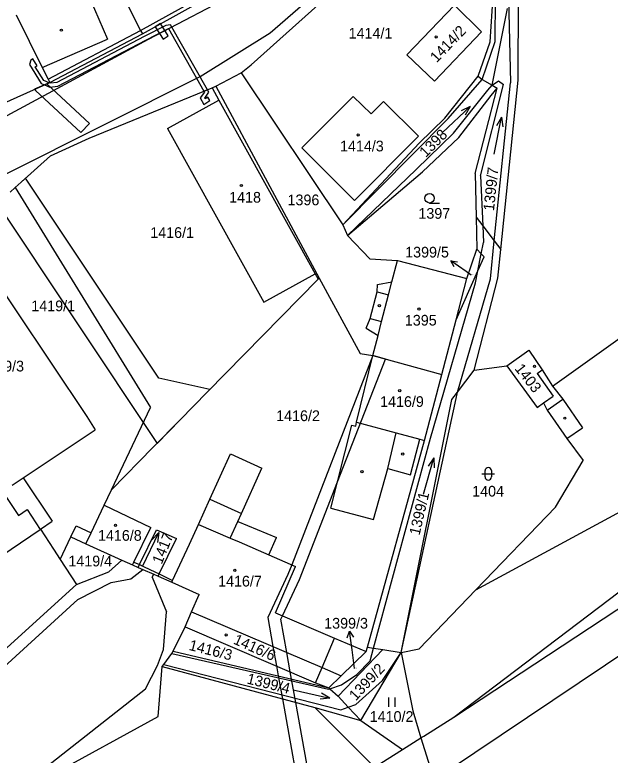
# Model space of a CAD drawing. Extents: x -785744 to -782822, y -1067550 to -1063910.
# Drawn here: x -784334.2 to -784239.5, y -1065522 to -1065404.3 of the extents above; entities that cross this region are included whole.
import ezdxf

# ---------------------------------------------------------------- set-up
doc = ezdxf.new("R2010")
doc.units = 0
for name, color, linetype in [('Hranice parcel', 7, 'Continuous'), ('Parcelní čísla', 7, 'Continuous'), ('Pop_ČP_popisy', 7, 'Continuous'), ('Vnitřní kresba', 7, 'Continuous'), ('Věcná břemena k části', 7, 'Continuous'), ('Značky budov', 7, 'Continuous'), ('Značky kultur', 7, 'Continuous')]:
    doc.layers.add(name, color=color, linetype=linetype)

msp = doc.modelspace()

# ---------------------------------------------------------------- linework, layer by layer
at = {"layer": 'Hranice parcel'}
for p, q in [((-784325.23, -1065487.26), (-784324.42, -1065485.54)), ((-784324.42, -1065485.54), (-784322.05, -1065486.66)), ((-784326.93, -1065490.87), (-784325.23, -1065487.26)), ((-784328.01, -1065489.21), (-784326.93, -1065490.87)), ((-784326.93, -1065490.87), (-784324.37, -1065494.83))]:
    msp.add_line(p, q, dxfattribs=at)
for points in [[(-784254.13, -1065414.69), (-784254.05, -1065388.02)], [(-784296.61, -1065412.23), (-784275.88, -1065393.63)], [(-784318.51, -1065398.12), (-784314.18, -1065406.77)], [(-784313.89, -1065407.3), (-784297.91, -1065398.39)], [(-784258.62, -1065408.55), (-784258.1, -1065401.22)], [(-784271.83, -1065410.63), (-784264.26, -1065402.73)], [(-784264.26, -1065402.73), (-784259.96, -1065406.99)], [(-784258.3, -1065415.48), (-784255.87, -1065403.26)], [(-784333.94, -1065404.27), (-784329.79, -1065412.66)], [(-784328.61, -1065415.04), (-784313.89, -1065407.3)], [(-784314.18, -1065406.77), (-784313.89, -1065407.3)], [(-784267.46, -1065414.82), (-784259.96, -1065406.99)], [(-784260.53, -1065414.01), (-784258.62, -1065408.55)], [(-784271.83, -1065410.63), (-784267.46, -1065414.82)], [(-784298.16, -1065413.48), (-784296.61, -1065412.23)], [(-784329.79, -1065412.66), (-784328.87, -1065414.51)], [(-784302.19, -1065415.64), (-784298.16, -1065413.48)], [(-784298.16, -1065413.48), (-784282.01, -1065437.69)], [(-784328.87, -1065414.51), (-784328.61, -1065415.04)], [(-784265.83, -1065420.7), (-784260.53, -1065414.01)], [(-784260.53, -1065414.01), (-784259.86, -1065414.56)], [(-784259.86, -1065414.56), (-784258.3, -1065415.48)], [(-784256.89, -1065441.59), (-784254.13, -1065414.69)], [(-784353.07, -1065426.03), (-784328.61, -1065415.04)], [(-784322.36, -1065423.91), (-784302.8, -1065415.89)], [(-784302.8, -1065415.89), (-784302.19, -1065415.64)], [(-784302.19, -1065415.64), (-784285.76, -1065446.13)], [(-784260.98, -1065429.49), (-784257.51, -1065415.94)], [(-784258.44, -1065417.09), (-784257.51, -1065415.94)], [(-784258.3, -1065415.48), (-784257.51, -1065415.94)], [(-784263.58, -1065423.8), (-784258.44, -1065417.09)], [(-784309.88, -1065422.37), (-784301.72, -1065417.85)], [(-784301.72, -1065417.85), (-784286.43, -1065445.44)], [(-784288.54, -1065425.41), (-784280.4, -1065417.25)], [(-784280.4, -1065417.25), (-784277.52, -1065420.02)], [(-784277.52, -1065420.02), (-784275.54, -1065418.04)], [(-784275.54, -1065418.04), (-784269.99, -1065423.58)], [(-784269.9, -1065424.7), (-784265.83, -1065420.7)], [(-784309.88, -1065422.37), (-784294.59, -1065449.96)], [(-784328.51, -1065426.7), (-784322.36, -1065423.91)], [(-784280.17, -1065433.79), (-784269.99, -1065423.58)], [(-784269.34, -1065429.22), (-784263.58, -1065423.8)], [(-784282.01, -1065437.69), (-784269.9, -1065424.7)], [(-784288.54, -1065425.41), (-784280.17, -1065433.79)], [(-784333.15, -1065430.88), (-784328.51, -1065426.7)], [(-784281.3, -1065439.38), (-784269.34, -1065429.22)], [(-784260.98, -1065429.49), (-784260.84, -1065436.43)], [(-784334.08, -1065431.72), (-784333.15, -1065430.88)], [(-784334.9, -1065432.46), (-784334.08, -1065431.72)], [(-784334.08, -1065431.72), (-784312.61, -1065466.7)], [(-784260.84, -1065436.43), (-784260.73, -1065441.54)], [(-784260.84, -1065436.43), (-784259.78, -1065437.82)], [(-784282.01, -1065437.69), (-784281.3, -1065439.38)], [(-784259.78, -1065437.82), (-784257.95, -1065440.21)], [(-784281.3, -1065439.38), (-784277.72, -1065443.08)], [(-784257.95, -1065440.21), (-784256.89, -1065441.59)], [(-784262.31, -1065446.22), (-784260.73, -1065441.54)], [(-784260.73, -1065441.54), (-784260.02, -1065442.28)], [(-784257.36, -1065446.16), (-784256.89, -1065441.59)], [(-784339.79, -1065442.71), (-784322.71, -1065468.16)], [(-784260.55, -1065445), (-784259.55, -1065442.76)], [(-784260.02, -1065442.28), (-784259.55, -1065442.76)], [(-784277.72, -1065443.08), (-784273.34, -1065443.33)], [(-784274.21, -1065446.71), (-784273.34, -1065443.33)], [(-784273.34, -1065443.33), (-784262.31, -1065446.22)], [(-784264.02, -1065452.76), (-784260.55, -1065445)], [(-784248.7, -1065463.3), (-784221.99, -1065444.26)], [(-784303.58, -1065464.28), (-784285.95, -1065446.31)], [(-784294.59, -1065449.96), (-784286.43, -1065445.44)], [(-784285.95, -1065446.31), (-784285.76, -1065446.13)], [(-784285.76, -1065446.13), (-784279.28, -1065458.15)], [(-784264.02, -1065452.76), (-784262.31, -1065446.22)], [(-784261.14, -1065460.78), (-784257.36, -1065446.16)], [(-784276.59, -1065448.34), (-784276.53, -1065447.13)], [(-784276.53, -1065447.13), (-784274.21, -1065446.71)], [(-784277.69, -1065452.58), (-784276.59, -1065448.34)], [(-784278.31, -1065454.07), (-784277.69, -1065452.58)], [(-784266.29, -1065461.45), (-784264.02, -1065452.76)], [(-784278.31, -1065454.07), (-784276.42, -1065455.25)], [(-784277.25, -1065458.45), (-784276.42, -1065455.25)], [(-784279.28, -1065458.15), (-784277.25, -1065458.45)], [(-784255.97, -1065460.11), (-784252.43, -1065457.59)], [(-784252.43, -1065457.59), (-784250.35, -1065460.73)], [(-784279.83, -1065469.05), (-784277.25, -1065458.45)], [(-784277.25, -1065458.45), (-784266.29, -1065461.45)], [(-784265.21, -1065524.39), (-784169.44, -1065460.07)], [(-784261.14, -1065460.78), (-784255.97, -1065460.11)], [(-784255.97, -1065460.11), (-784251.14, -1065466.73)], [(-784269.04, -1065471.94), (-784266.29, -1065461.45)], [(-784263.77, -1065464.25), (-784261.14, -1065460.78)], [(-784250.35, -1065460.73), (-784248.7, -1065463.3)], [(-784264.37, -1065515.96), (-784195.4, -1065463.66)], [(-784248.7, -1065463.3), (-784247.06, -1065465.4)], [(-784307.87, -1065468.67), (-784303.58, -1065464.28)], [(-784264.67, -1065465.45), (-784263.77, -1065464.25)], [(-784247.06, -1065465.4), (-784243.93, -1065469.93)], [(-784272.77, -1065505.68), (-784264.67, -1065465.45)], [(-784251.14, -1065466.73), (-784250.11, -1065465.98)], [(-784250.11, -1065465.98), (-784249.54, -1065467.11)], [(-784318.81, -1065479.81), (-784312.61, -1065466.7)], [(-784249.54, -1065467.11), (-784246.41, -1065471.64)], [(-784322.71, -1065468.16), (-784321.4, -1065470.26)], [(-784312.17, -1065473.04), (-784307.87, -1065468.67)], [(-784283.91, -1065482.7), (-784280.58, -1065469.52)], [(-784280.58, -1065469.52), (-784279.98, -1065469.66)], [(-784279.98, -1065469.66), (-784279.83, -1065469.05)], [(-784246.41, -1065471.64), (-784243.93, -1065469.93)], [(-784332.82, -1065477.89), (-784321.4, -1065470.26)], [(-784278.12, -1065504.82), (-784269.04, -1065471.94)], [(-784271.28, -1065477.43), (-784269.76, -1065471.74)], [(-784269.76, -1065471.74), (-784269.04, -1065471.94)], [(-784246.41, -1065471.64), (-784243.8, -1065475.13)], [(-784318.81, -1065479.81), (-784312.17, -1065473.04)], [(-784303.16, -1065481.3), (-784299.9, -1065474.1)], [(-784299.9, -1065474.1), (-784294.89, -1065476.37)], [(-784248.23, -1065482.58), (-784243.8, -1065475.13)], [(-784298.15, -1065483.57), (-784294.89, -1065476.37)], [(-784277.13, -1065484.5), (-784274.89, -1065476.42)], [(-784274.89, -1065476.42), (-784271.28, -1065477.43)], [(-784332.82, -1065477.89), (-784328.21, -1065484.8)], [(-784260.87, -1065495.71), (-784230.15, -1065479.08)], [(-784319.95, -1065482.23), (-784318.81, -1065479.81)], [(-784304.98, -1065485.31), (-784303.16, -1065481.3)], [(-784322.05, -1065486.66), (-784319.95, -1065482.23)], [(-784319.95, -1065482.23), (-784312.53, -1065485.78)], [(-784283.91, -1065482.7), (-784277.13, -1065484.5)], [(-784260.87, -1065495.71), (-784248.23, -1065482.58)], [(-784298.73, -1065484.84), (-784298.15, -1065483.57)], [(-784330.06, -1065486.04), (-784328.21, -1065484.8)], [(-784306.4, -1065488.45), (-784304.98, -1065485.31)], [(-784298.73, -1065484.84), (-784292.58, -1065487.39)], [(-784337.91, -1065491.33), (-784330.13, -1065486.09)], [(-784330.13, -1065486.09), (-784330.06, -1065486.04)], [(-784330.06, -1065486.04), (-784328.01, -1065489.21)], [(-784315.22, -1065491.28), (-784312.53, -1065485.78)], [(-784314.35, -1065491.69), (-784311.65, -1065486.16)], [(-784311.65, -1065486.16), (-784308.47, -1065487.55)], [(-784322.86, -1065488.38), (-784322.05, -1065486.66)], [(-784311.2, -1065493.18), (-784308.47, -1065487.55)], [(-784293.78, -1065490.14), (-784292.58, -1065487.39)], [(-784322.86, -1065488.38), (-784317.15, -1065490.98)], [(-784309.07, -1065494.2), (-784306.4, -1065488.45)], [(-784264.37, -1065515.96), (-784223.44, -1065488.95)], [(-784319.21, -1065492.84), (-784317.15, -1065490.98)], [(-784317.15, -1065490.98), (-784315.43, -1065491.75)], [(-784315.43, -1065491.75), (-784315.22, -1065491.28)], [(-784293.78, -1065490.14), (-784289.57, -1065491.99)], [(-784315.43, -1065491.75), (-784314.56, -1065492.13)], [(-784314.56, -1065492.13), (-784314.35, -1065491.69)], [(-784314.56, -1065492.13), (-784313.8, -1065492.46)], [(-784313.8, -1065492.46), (-784312.06, -1065493.22)], [(-784292.73, -1065499.34), (-784289.57, -1065491.99)], [(-784324.37, -1065494.83), (-784319.21, -1065492.84)], [(-784312.06, -1065493.22), (-784311.37, -1065493.53)], [(-784311.37, -1065493.53), (-784311.2, -1065493.18)], [(-784311.37, -1065493.53), (-784309.2, -1065494.48)], [(-784351.69, -1065519.66), (-784324.37, -1065494.83)], [(-784309.2, -1065494.48), (-784309.07, -1065494.2)], [(-784309.2, -1065494.48), (-784304.84, -1065496.42)], [(-784269.89, -1065505.08), (-784260.87, -1065495.71)], [(-784306.05, -1065499.18), (-784304.84, -1065496.42)], [(-784307.09, -1065501.56), (-784306.05, -1065499.18)], [(-784306.05, -1065499.18), (-784285.33, -1065508.05)], [(-784292.73, -1065499.34), (-784283.32, -1065503.38)], [(-784308.97, -1065505.47), (-784307.09, -1065501.56)], [(-784307.09, -1065501.56), (-784286.36, -1065510.46)], [(-784285.33, -1065508.05), (-784283.32, -1065503.38)], [(-784282.78, -1065512.6), (-784275.65, -1065505.21)], [(-784278.31, -1065505.52), (-784278.12, -1065504.82)], [(-784278.12, -1065504.82), (-784277.13, -1065504.98)], [(-784277.13, -1065504.98), (-784275.65, -1065505.21)], [(-784275.65, -1065505.21), (-784272.77, -1065505.68)], [(-784272.77, -1065505.68), (-784269.89, -1065505.08)], [(-784310.49, -1065507.55), (-784309.22, -1065505.81)], [(-784309.22, -1065505.81), (-784308.97, -1065505.47)], [(-784308.97, -1065505.47), (-784284.27, -1065511.27)], [(-784282.28, -1065509.35), (-784278.31, -1065505.52)], [(-784279.17, -1065516.47), (-784272.77, -1065505.68)], [(-784272.77, -1065505.68), (-784270.92, -1065514.95)], [(-784310.75, -1065507.9), (-784310.49, -1065507.55)], [(-784311.36, -1065515.82), (-784310.75, -1065507.9)], [(-784310.75, -1065507.9), (-784286.46, -1065514.42)], [(-784286.36, -1065510.46), (-784285.33, -1065508.05)], [(-784285.33, -1065508.05), (-784282.28, -1065509.35)], [(-784284.27, -1065511.27), (-784282.28, -1065509.35)], [(-784284.27, -1065511.27), (-784284.1, -1065511.42)], [(-784284.1, -1065511.42), (-784282.78, -1065512.6)], [(-784282.78, -1065512.6), (-784281.15, -1065514.35)], [(-784286.46, -1065514.42), (-784279.17, -1065516.47)], [(-784281.15, -1065514.35), (-784279.17, -1065516.47)], [(-784328.38, -1065525.17), (-784311.36, -1065515.82)], [(-784270.92, -1065514.95), (-784269.6, -1065519.25)], [(-784269.16, -1065518.98), (-784264.37, -1065515.96)], [(-784279.17, -1065516.47), (-784272.55, -1065521.1)], [(-784272.55, -1065521.1), (-784269.6, -1065519.25)], [(-784269.6, -1065519.25), (-784269.16, -1065518.98)], [(-784269.6, -1065519.25), (-784267.63, -1065525.66)], [(-784276.98, -1065523.88), (-784272.55, -1065521.1)]]:
    msp.add_lwpolyline(points, dxfattribs=at)
at = {"layer": 'Pop_ČP_popisy'}
for p, q in [((-784262.42, -1065445.1), (-784264.87, -1065443.37)), ((-784280.56, -1065505.25), (-784280.95, -1065502.28))]:
    msp.add_line(p, q, dxfattribs=at)
for points in [[(-784264.34, -1065444.36), (-784264.87, -1065443.37), (-784263.77, -1065443.54)], [(-784261.62, -1065445.66), (-784262.42, -1065445.1)], [(-784281.32, -1065503.33), (-784280.95, -1065502.28), (-784280.33, -1065503.2)], [(-784280.17, -1065508.19), (-784280.56, -1065505.25)]]:
    msp.add_lwpolyline(points, dxfattribs=at)
at = {"layer": 'Vnitřní kresba'}
for points in [[(-784314.18, -1065406.77), (-784298.2, -1065397.86)], [(-784293.59, -1065407.12), (-784283.18, -1065398.1)], [(-784312.91, -1065408.16), (-784297.89, -1065400.23)], [(-784322.2, -1065401.72), (-784319.44, -1065408.15)], [(-784257.82, -1065408.51), (-784257.74, -1065401.55)], [(-784255.68, -1065401.64), (-784255.35, -1065415.08)], [(-784328.87, -1065414.51), (-784314.18, -1065406.77)], [(-784304.68, -1065414.1), (-784293.59, -1065407.12)], [(-784336.08, -1065420.66), (-784312.91, -1065408.16)], [(-784329.79, -1065412.66), (-784319.44, -1065408.15)], [(-784259.86, -1065414.56), (-784257.82, -1065408.51)], [(-784335.41, -1065429.53), (-784304.68, -1065414.1)], [(-784265.26, -1065420.75), (-784259.86, -1065414.56)], [(-784258.3, -1065415.48), (-784257.27, -1065414.76)], [(-784257.27, -1065414.76), (-784256.49, -1065415.35)], [(-784302.8, -1065415.89), (-784301.72, -1065417.85)], [(-784260.14, -1065429.88), (-784256.49, -1065415.35)], [(-784258.96, -1065416.26), (-784258.3, -1065415.48)], [(-784257.95, -1065440.21), (-784255.35, -1065415.08)], [(-784264.41, -1065423.08), (-784258.96, -1065416.26)], [(-784282.01, -1065437.69), (-784265.26, -1065420.75)], [(-784270.38, -1065428.87), (-784264.41, -1065423.08)], [(-784281.3, -1065439.38), (-784270.38, -1065428.87)], [(-784260.14, -1065429.88), (-784259.78, -1065437.82)], [(-784259.78, -1065437.82), (-784259.66, -1065440.47)], [(-784260.02, -1065442.28), (-784259.66, -1065440.47)], [(-784258.57, -1065446.23), (-784257.95, -1065440.21)], [(-784260.55, -1065445), (-784260.02, -1065442.28)], [(-784260.92, -1065446.87), (-784260.55, -1065445)], [(-784286.43, -1065445.44), (-784285.95, -1065446.31)], [(-784263.77, -1065464.25), (-784258.57, -1065446.23)], [(-784274.75, -1065448.81), (-784274.21, -1065446.71)], [(-784268.08, -1065471.6), (-784260.92, -1065446.87)], [(-784276.59, -1065448.34), (-784274.75, -1065448.81)], [(-784275.85, -1065453.05), (-784274.75, -1065448.81)], [(-784277.69, -1065452.58), (-784275.85, -1065453.05)], [(-784276.42, -1065455.25), (-784275.85, -1065453.05)], [(-784251.14, -1065461.29), (-784250.35, -1065460.73)], [(-784251.14, -1065461.29), (-784248.61, -1065464.89)], [(-784272.77, -1065505.68), (-784264.03, -1065465.3)], [(-784264.03, -1065465.3), (-784263.77, -1065464.25)], [(-784250.11, -1065465.98), (-784248.61, -1065464.89)], [(-784249.54, -1065467.11), (-784247.06, -1065465.4)], [(-784279.83, -1065469.05), (-784273.57, -1065470.72)], [(-784274.89, -1065476.42), (-784273.57, -1065470.72)], [(-784273.57, -1065470.72), (-784269.76, -1065471.74)], [(-784277.13, -1065504.98), (-784268.08, -1065471.6)], [(-784334.58, -1065479.06), (-784332.82, -1065477.89)], [(-784336.12, -1065480.09), (-784333.6, -1065483.86)], [(-784303.16, -1065481.3), (-784298.15, -1065483.57)], [(-784333.6, -1065483.86), (-784332.21, -1065482.94)], [(-784332.21, -1065482.94), (-784330.13, -1065486.09)], [(-784304.98, -1065485.31), (-784299.92, -1065487.47)], [(-784299.92, -1065487.47), (-784298.73, -1065484.84)], [(-784325.23, -1065487.26), (-784322.86, -1065488.38)], [(-784299.92, -1065487.47), (-784298.5, -1065488.07)], [(-784298.5, -1065488.07), (-784293.78, -1065490.14)], [(-784315.22, -1065491.28), (-784314.35, -1065491.69)], [(-784315.73, -1065493.94), (-784313.8, -1065492.46)], [(-784314.35, -1065491.69), (-784313.6, -1065492.04)], [(-784313.6, -1065492.04), (-784311.89, -1065492.85)], [(-784312.32, -1065493.7), (-784312.06, -1065493.22)], [(-784311.89, -1065492.85), (-784311.2, -1065493.18)], [(-784311.2, -1065493.18), (-784309.07, -1065494.2)], [(-784324.13, -1065497.26), (-784318.87, -1065494.54)], [(-784318.87, -1065494.54), (-784315.73, -1065493.94)], [(-784312.32, -1065493.7), (-784310.06, -1065499.22)], [(-784354.42, -1065524.84), (-784324.13, -1065497.26)], [(-784310.53, -1065505.21), (-784310.06, -1065499.22)], [(-784283.32, -1065503.38), (-784278.31, -1065505.52)], [(-784311.46, -1065507.74), (-784310.53, -1065505.21)], [(-784277.68, -1065507), (-784277.13, -1065504.98)], [(-784309.22, -1065505.81), (-784284.3, -1065511.49)], [(-784275.72, -1065510.13), (-784272.77, -1065505.68)], [(-784313.37, -1065511.43), (-784311.46, -1065507.74)], [(-784310.49, -1065507.55), (-784282.33, -1065514.77)], [(-784279.81, -1065509.18), (-784277.68, -1065507)], [(-784282.23, -1065510.81), (-784279.81, -1065509.18)], [(-784279.94, -1065513.92), (-784275.72, -1065510.13)], [(-784286.36, -1065510.46), (-784284.27, -1065511.27)], [(-784284.1, -1065511.42), (-784282.23, -1065510.81)], [(-784329.77, -1065524.34), (-784313.37, -1065511.43)], [(-784284.3, -1065511.49), (-784284.1, -1065511.42)], [(-784286.46, -1065514.42), (-784276.98, -1065523.88)], [(-784282.33, -1065514.77), (-784281.15, -1065514.35)], [(-784281.15, -1065514.35), (-784279.94, -1065513.92)]]:
    msp.add_lwpolyline(points, dxfattribs=at)
at = {"layer": 'Věcná břemena k části'}
for points in [[(-784310.13, -1065405.97), (-784313.61, -1065407.75)], [(-784313.33, -1065408.29), (-784309.75, -1065406.45)], [(-784310.99, -1065405.68), (-784311.87, -1065406.17)], [(-784311.87, -1065406.17), (-784310.6, -1065408.17)], [(-784309.76, -1065407.63), (-784310.99, -1065405.68)], [(-784309.39, -1065405.86), (-784310.13, -1065405.97)], [(-784309.75, -1065406.45), (-784304.1, -1065416.42)], [(-784303.54, -1065416.19), (-784309.39, -1065405.86)], [(-784310.6, -1065408.17), (-784309.76, -1065407.63)], [(-784313.61, -1065407.75), (-784327.48, -1065415.06)], [(-784327.3, -1065415.64), (-784313.33, -1065408.29)], [(-784331.64, -1065411.46), (-784331.84, -1065412.2)], [(-784331.84, -1065412.2), (-784329.97, -1065415.18)], [(-784331.3, -1065411.26), (-784331.64, -1065411.46)], [(-784330.63, -1065412.41), (-784331.3, -1065411.26)], [(-784330.9, -1065412.57), (-784330.63, -1065412.41)], [(-784329.57, -1065414.7), (-784330.9, -1065412.57)], [(-784328.69, -1065415.08), (-784329.57, -1065414.7)], [(-784329.05, -1065415.24), (-784331.01, -1065416.12)], [(-784329.97, -1065415.18), (-784329.44, -1065415.41)], [(-784328.69, -1065415.08), (-784329.44, -1065415.41)], [(-784329.44, -1065415.41), (-784328.69, -1065415.08)], [(-784329.44, -1065415.41), (-784328.59, -1065415.78)], [(-784322.28, -1065421.53), (-784329.05, -1065415.24)], [(-784328.49, -1065415.16), (-784328.69, -1065415.08)], [(-784328.59, -1065415.78), (-784327.3, -1065415.64)], [(-784327.48, -1065415.06), (-784328.49, -1065415.16)], [(-784331.01, -1065416.12), (-784330.85, -1065416.29)], [(-784330.85, -1065416.29), (-784323.64, -1065422.99)], [(-784304.03, -1065416.55), (-784304.69, -1065417.47)], [(-784303.54, -1065416.19), (-784304.1, -1065416.42)], [(-784304.1, -1065416.42), (-784303.54, -1065416.19)], [(-784304.1, -1065416.42), (-784304.03, -1065416.55)], [(-784303.97, -1065417.51), (-784303.31, -1065416.59)], [(-784303.31, -1065416.59), (-784303.54, -1065416.19)], [(-784304.69, -1065417.47), (-784304.09, -1065418.51)], [(-784304.09, -1065418.51), (-784303.16, -1065417.88)], [(-784303.89, -1065417.65), (-784303.97, -1065417.51)], [(-784303.5, -1065417.38), (-784303.89, -1065417.65)], [(-784303.16, -1065417.88), (-784303.5, -1065417.38)], [(-784323.64, -1065422.99), (-784322.28, -1065421.53)], [(-784333.15, -1065430.88), (-784334.08, -1065431.72)], [(-784332.47, -1065430.27), (-784333.15, -1065430.88)], [(-784311.26, -1065462.04), (-784332.47, -1065430.27)], [(-784334.08, -1065431.72), (-784334.9, -1065432.46)], [(-784337.35, -1065433.77), (-784311.55, -1065472.41)], [(-784285.98, -1065533.43), (-784286.13, -1065532.33), (-784286.36, -1065531.04), (-784289.5, -1065513.6), (-784290.17, -1065509.89), (-784290.37, -1065508.74), (-784290.93, -1065505.65), (-784291.88, -1065500.36), (-784291.62, -1065499.81), (-784288.92, -1065494.07), (-784282.86, -1065478.53), (-784275.24, -1065459), (-784277.25, -1065458.45), (-784290.15, -1065491.73), (-784290.75, -1065493.28), (-784293.96, -1065500.08), (-784293.13, -1065504.71), (-784292.58, -1065507.79), (-784292.29, -1065509.39), (-784291.63, -1065513.03), (-784288.15, -1065532.41), (-784287.96, -1065533.75)], [(-784303.15, -1065463.85), (-784311.26, -1065462.04)], [(-784303.58, -1065464.28), (-784303.15, -1065463.85)], [(-784307.87, -1065468.67), (-784303.58, -1065464.28)], [(-784311.55, -1065472.41), (-784307.87, -1065468.67)]]:
    msp.add_lwpolyline(points, dxfattribs=at)
at = {"layer": 'Značky budov'}
for centre in [(-784326.75, -1065406.71), (-784267.19, -1065407.8), (-784279.58, -1065423.38), (-784298.14, -1065431.41), (-784276.21, -1065450.52), (-784269.93, -1065451.06), (-784251.55, -1065460.18), (-784272.98, -1065464.04), (-784246.73, -1065468.41), (-784272.51, -1065474.11), (-784278.99, -1065476.92), (-784318.15, -1065485.44), (-784299.19, -1065492.59), (-784300.56, -1065502.88)]:
    msp.add_circle(centre, 0.175, dxfattribs=at)
at = {"layer": 'Značky kultur'}
for p, q in [((-784268.23, -1065434.2), (-784266.63, -1065434.2)), ((-784259.41, -1065477.75), (-784259.41, -1065476.75)), ((-784258.41, -1065476.75), (-784258.41, -1065477.75)), ((-784259.91, -1065477.25), (-784257.91, -1065477.25)), ((-784274.72, -1065514.3), (-784274.72, -1065512.8)), ((-784273.72, -1065514.3), (-784273.72, -1065512.8))]:
    msp.add_line(p, q, dxfattribs=at)
for points in [[(-784266.16, -1065422.97), (-784261.8, -1065418.85), (-784263.23, -1065419.52)], [(-784261.8, -1065418.85), (-784262.55, -1065420.24)], [(-784257.98, -1065426.42), (-784256.8, -1065420.54), (-784257.58, -1065421.91)], [(-784256.8, -1065420.54), (-784256.6, -1065422.11)], [(-784269.21, -1065480.48), (-784267.55, -1065474.72), (-784268.44, -1065476.02)], [(-784267.55, -1065474.72), (-784267.48, -1065476.3)], [(-784313.85, -1065492.01), (-784311.27, -1065486.59), (-784312.37, -1065487.73)], [(-784311.27, -1065486.59), (-784311.46, -1065488.16)], [(-784289.93, -1065511.62), (-784284.07, -1065512.94), (-784285.43, -1065512.12)], [(-784284.07, -1065512.94), (-784285.65, -1065513.1)]]:
    msp.add_lwpolyline(points, dxfattribs=at)
msp.add_circle((-784268.23, -1065433.45), 0.75, dxfattribs=at)
for centre, start, end in [((-784258.91, -1065476.75), 0, 180), ((-784258.91, -1065477.75), 180, 0)]:
    msp.add_arc(centre, 0.5, start, end, dxfattribs=at)

# ---------------------------------------------------------------- texts
at = {"layer": 'Parcelní čísla'}
for s, height, p in [('1414/1', 1.7, (-784281.1, -1065408.05)), ('1414/3', 1.7, (-784282.47, -1065425.99)), ('1418', 1.7, (-784300.09, -1065434.14)), ('1396', 1.7, (-784290.81, -1065434.55)), ('1397', 1.7, (-784270.01, -1065436.7)), ('1416/1', 1.7, (-784312.63, -1065439.75)), ('1399/5', 0.1, (-784261.62, -1065445.66)), ('1419/1', 1.7, (-784331.54, -1065451.4)), ('1395', 1.7, (-784272.16, -1065453.68)), ('1419/3', 1.7, (-784339.65, -1065460.98)), ('1416/9', 1.7, (-784276.1, -1065466.62)), ('1416/2', 1.7, (-784292.62, -1065468.87)), ('1404', 1.7, (-784261.46, -1065480.87)), ('1416/8', 1.7, (-784320.94, -1065487.9)), ('1419/4', 1.7, (-784325.65, -1065491.97)), ('1416/7', 1.7, (-784301.85, -1065495.17)), ('1399/3', 0.1, (-784280.17, -1065508.19)), ('1410/2', 1.7, (-784277.75, -1065516.69))]:
    msp.add_text(s, height=height, dxfattribs=at).set_placement(p)
for s, rotation, p in [('1414/2', 46.2086, (-784267.11, -1065411.98)), ('1398', 45, (-784268.84, -1065427.06)), ('1399/7', 84.018, (-784258, -1065435.52)), ('1403', 308.2982, (-784254.79, -1065460.56)), ('1399/1', 76.8871, (-784269.84, -1065487.13)), ('1417', 67.775, (-784310.82, -1065491.74)), ('1416/6', 335.9864, (-784299.55, -1065504.21)), ('1416/3', 345.8543, (-784306.59, -1065505.24)), ('1399/2', 47.011, (-784279.96, -1065513.44)), ('1399/4', 346.0641, (-784297.4, -1065510.57))]:
    msp.add_text(s, height=1.7, rotation=rotation, dxfattribs=at).set_placement(p)
at = {"layer": 'Pop_ČP_popisy'}
for s, p in [('1399/5', (-784272.11, -1065442.86)), ('1399/3', (-784284.98, -1065501.86))]:
    msp.add_text(s, height=1.7, dxfattribs=at).set_placement(p)

doc.saveas('drawing.dxf')
